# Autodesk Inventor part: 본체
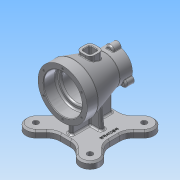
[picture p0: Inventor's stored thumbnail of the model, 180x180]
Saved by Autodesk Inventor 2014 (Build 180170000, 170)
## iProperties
Created: 2018-03
Part Number: 본체
Material: 알루미늄 6061
Document SubType Name: Modeling
Designer: 703
Density: 2.71 g/cm^3
Appearance: 알루미늄 - 평지
Mass: 955.084 g
Surface Area: 847.115 cm^2
Volume: 352.429 cm^3
Author: 703
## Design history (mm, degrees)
sketch "스케치1"
  geometry: L1 (45, -45)-(-45, -45); L2 (-45, -45)-(-45, 45); L3 (-45, 45)-(45, 45); L4 (45, 45)-(45, -45); L5 (45, -45)-(-45, 45); L6 (-45, -45)-(45, 45); 1 further point
  constraints: 12 end point, 2 midpoint, 2 parallel, 1 horizontal, 1 perpendicular
  dimensions: "d0" = 90 distance of L2.end L3.end; "d1" = 90 distance of L1.end L2.end
extrude "돌출1" new body sketch "스케치1" distance "d2" = 12; taper "d3" = 0 deg
sketch "스케치2" dims "d4" = 140
  geometry: L1 (45, -45)-(45, 45) reference; L2 (45, 45)-(-45, 45) reference; L3 (0, 0)-(53.436, 53.436); L4 (0, 0)-(75.571, 0); L5 (36.77, 62.225)-(19.544, 45); L6 (62.225, 36.77)-(45, 19.544); A1 r 18 centre (49.497, 49.497) between (62.225, 36.77) and (36.77, 62.225); 1 further point
  constraints: 8 end point, 3 point on line, 2 parallel, 2 point on circle, 2 tangent, 1 centre point, 1 coincident, 1 equal length, 1 horizontal, 3 other
  dimensions: "d5" = 45 deg angle of L4 L3; "d6" = 36 diameter of A1
extrude "돌출2" join sketch "스케치2" distance "d7" = 12; taper "d8" = 0 deg
sketch "스케치3"
  geometry: L1 (-50, 82)-(50, 82); L2 (-50, 82)-(-50, 127); L3 (-50, 127)-(-30, 127); L4 (-30, 127)-(27, 109.5); L5 (27, 109.5)-(50, 109.5); L6 (50, 109.5)-(50, 82); 2 further points
  constraints: 12 end point, 2 perpendicular, 1 horizontal, 1 midpoint, 1 parallel, 1 vertical alignment
  dimensions: "d12" = 82 distance from line of point (0, 0) L1; "d13" = 20 distance of L2.end L3.end; "d14" = 90 diameter of L3 L1; "d15" = 100 distance between parallel lines of L6 L2; "d16" = 77 horizontal distance of L2.end L4.end; "d17" = 55 diameter of L5 L1
revolve "회전1" sketch "스케치3" stored, may be unused: angle "d18" = 90 deg
sketch "스케치5"
  geometry: L1 (-37, 12)-(37, 12); L2 (37, 12)-(37, 70); L3 (37, 70)-(-37, 70); L4 (-37, 70)-(-37, 12); L5 (-37, 12)-(37, 70); L6 (37, 12)-(-37, 70); L7 (19.544, 12)-(-19.544, 12) reference; 3 further points
  constraints: 12 end point, 3 midpoint, 2 parallel, 1 collinear, 1 horizontal, 1 perpendicular, 1 vertical alignment
  dimensions: "d25" = 37 distance from line of point (0, 0) L4; "d26" = 70 distance from line of point (0, 0) L3
extrude "돌출3" join sketch "스케치5" stored distance "d27" = 8; taper "d28" = 0 deg
sketch "스케치6"
  geometry: L1 (-19.801, 60)-(-24, 12); L2 (-24, 12)-(24, 12); L3 (-36.77, 12)-(-67.497, 12) reference; L4 (-19.801, 60)-(19.801, 60); L5 (-36.77, 12)-(-19.544, 12) reference; L6 (24, 12)-(19.801, 60); L7 (67.497, 12)-(36.77, 12) reference; 3 further points
  constraints: 8 end point, 2 collinear, 1 parallel
  dimensions: "d29" = 24 horizontal distance of point (0, 0) L1.end; "d30" = 95 deg angle of L5 L1; "d32" = 24 horizontal distance of point (0, 0) L2.end; "d33" = 60 distance from line of point (0, 0) L4; "d34" = 95 deg angle of L7 L6
extrude "돌출4" join sketch "스케치6" stored distance "d35" = 8; taper "d36" = 0 deg
sketch "스케치4"
  geometry: L1 (-50, 37)-(-50, 127) reference; L2 (-50, 82)-(50, 82); L3 (-50, 82)-(-50, 117); L4 (-50, 117)-(-30, 117); L5 (-27, 114)-(-27, 111); L6 (-24, 108)-(17, 108); L7 (20, 105)-(20, 105); L8 (23, 102)-(50, 102); L9 (50, 54.5)-(50, 109.5) reference; L10 (50, 102)-(50, 82); A1 r 3 centre (-30, 114) between (-27, 114) and (-30, 117); A2 r 3 centre (-24, 111) between (-27, 111) and (-24, 108); A3 r 3 centre (17, 105) between (20, 105) and (17, 108); A4 r 3 centre (23, 105) between (20, 105) and (23, 102); 4 further points
  constraints: 16 end point, 8 point on circle, 8 point on line, 8 tangent, 4 centre point, 3 equal radius, 3 perpendicular, 2 parallel, 1 collinear, 1 midpoint, 1 vertical
  dimensions: "d19" = 40 diameter of L8 L2; "d20" = 52 diameter of L6 L2; "d21" = 23 distance of L3.end point (-27, 117); "d22" = 70 diameter of L4 L2; "d23" = 47 distance of point (-27, 108) point (20, 108); "d24" = 3 radius of A1
revolve "회전2" sketch "스케치4" stored, may be unused: angle "d37" = 90 deg
chamfer "모따기1" distance "d38" = 1; stored, may be unused: second distance "d39" = 2, angle "d40" = 45 deg
node "작업 평면1"
sketch "스케치7"
  geometry: L1 (-12.5, 12.5)-(12.5, 12.5); L2 (12.5, 12.5)-(12.5, -12.5); L3 (12.5, -12.5)-(-12.5, -12.5); L4 (-12.5, -12.5)-(-12.5, 12.5); L5 (-12.5, 12.5)-(12.5, -12.5); L6 (12.5, 12.5)-(-12.5, -12.5); 1 further point
  constraints: 12 end point, 2 midpoint, 2 parallel, 1 horizontal, 1 perpendicular
  dimensions: "d42" = 25 distance of L2.end L3.end; "d43" = 25 distance of L1.end L2.end
extrude "돌출5" join sketch "스케치7" stored distance "d44" = 8; taper "d45" = 0 deg
sketch "스케치8"
  geometry: L1 (-7.5, -7.5)-(7.5, -7.5); L2 (7.5, -7.5)-(7.5, 7.5); L3 (7.5, 7.5)-(-7.5, 7.5); L4 (-7.5, 7.5)-(-7.5, -7.5); L5 (-7.5, -7.5)-(7.5, 7.5); L6 (7.5, -7.5)-(-7.5, 7.5); 1 further point
  constraints: 12 end point, 2 midpoint, 2 parallel, 1 horizontal, 1 perpendicular
  dimensions: "d46" = 15 distance of L3.end L2.end; "d47" = 15 distance of L2.end L1.end
extrude "돌출6" cut sketch "스케치8" stored distance "d48" = 8; taper "d49" = 0 deg
fillet "모깎기1" dims "d50" = 8
fillet "모깎기2" dims "d51" = 3
sketch "스케치9"
  geometry: A1 r 27.5 centre (0, 0) between (0, -27.5) and (6.943, -26.609) reference; A2 r 7 centre (0, -27.5) between (-6.943, -26.609) and (6.943, -26.609); 1 further point
  constraints: 5 point on circle, 1 centre point, 1 vertical alignment
  dimensions: "d53" = 7 radius of A2
extrude "돌출7" join sketch "스케치9" distance "d54" = 15; taper "d55" = 0 deg
fillet "모깎기3" dims "d56" = 3
fillet "모깎기4" dims "d57" = 1
sketch "스케치10"
  geometry: A1 r 7 centre (0, 0) between (-6.999, 0.127) and (6.999, 0.127) reference; 1 further point
hole "구멍1" sketch "스케치10" at (0, 0) diameter "d58" = 3.242; stored, may be unused: countersink angle "d62" = 90 deg, drill point angle "d64" = 118 deg; dims "d59" = 9, "d60" = 4, "d61" = 2, "d63" = 11
fillet "모깎기5" dims "d68" = 3
fillet "모깎기6" dims "d69" = 25
fillet "모깎기7" dims "d70" = 3
fillet "모깎기8" dims "d71" = 3
fillet "모깎기9" dims "d72" = 1
sketch "스케치11"
  geometry: A1 r 15 centre (-49.497, 49.497) between (-38.891, 60.104) and (-60.104, 38.891) reference; A2 r 15 centre (-49.497, -49.497) between (-60.104, -38.891) and (-38.891, -60.104) reference; A3 r 15 centre (49.497, -49.497) between (38.891, -60.104) and (60.104, -38.891) reference; A4 r 15 centre (49.497, 49.497) between (60.104, 38.891) and (38.891, 60.104) reference; 1 further point
hole "구멍2" sketch "스케치11" at (-49.497, -49.497), (49.497, -49.497), (49.497, 49.497), (-49.497, 49.497) diameter "d73" = 10; stored, may be unused: countersink angle "d77" = 90 deg, drill point angle "d79" = 118 deg; dims "d74" = 9, "d75" = 4, "d76" = 2, "d78" = 11
sketch "스케치12"
  geometry: C1 r 45 at (0, 0) reference; C2 r 36 at (0, 0) reference; 7 further points
  constraints: 1 vertical alignment, 7 other
  dimensions: "d80" = 40 distance of C1.centre point (0, 40); "d83" = 360 deg dimension on C2.centre point (0, 40) (derived)
hole "구멍3" sketch "스케치12" at (0, 40), (-34.641, 20), (-34.641, -20), (0, -40), (34.641, -20), (34.641, 20) diameter "d85" = 3.242; stored, may be unused: countersink angle "d89" = 90 deg, drill point angle "d91" = 118 deg; dims "d86" = 9, "d87" = 4, "d88" = 2, "d90" = 11
chamfer "모따기2" distance "d92" = 1; stored, may be unused: second distance "d93" = 2, angle "d94" = 45 deg
chamfer "모따기3" distance "d95" = 3; stored, may be unused: second distance "d96" = 2, angle "d97" = 45 deg
sketch "스케치13"
  geometry: L1 (9.189, 45)-(-9.189, 45) reference; 2 further points
  constraints: 1 other
  dimensions: "d98" = 35 distance of point (35, 0) point (0, 0); "d99" = 45 distance from line of point (35, 0) L1
feature "엠보싱1" sketch "스케치13" dims "d0" = 90, "d1" = 90, "d100" = 0.5, "d101" = 0
node "솔리드1"
pattern_circular "원형 패턴1" dims angle "d10" = 360 deg
pattern_circular "원형 패턴2" dims "d66" = 360 deg
other parameters: "d41" = 127, "d52" = 14
